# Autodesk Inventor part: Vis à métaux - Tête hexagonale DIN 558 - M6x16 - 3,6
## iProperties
Created: 2002-09
Part Number: Vis à métaux - Tête hexagonale DIN 558 - M6x16 - 3,6
Material: Par défaut
Catalog Web Link: www.traceparts.com
Description: Vis à métaux - Tête hexagonale DIN 558 - M6x16 - 3,6
Document SubType Name: Modélisation
Designer: Maison
Control State: 0
Master: False
Checked Out: False
Shininess: 20.0
Length Units: 11269
Angle Units: 11279
Time Units: 11290
Mass Units: 11283
Length Display Precision: 3
Angle Display Precision: 2
Density: 0.0
Volumn: 0.0
Area: 0.0
PropertySet Name: Model Information
Author: Maison
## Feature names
1. Base1
